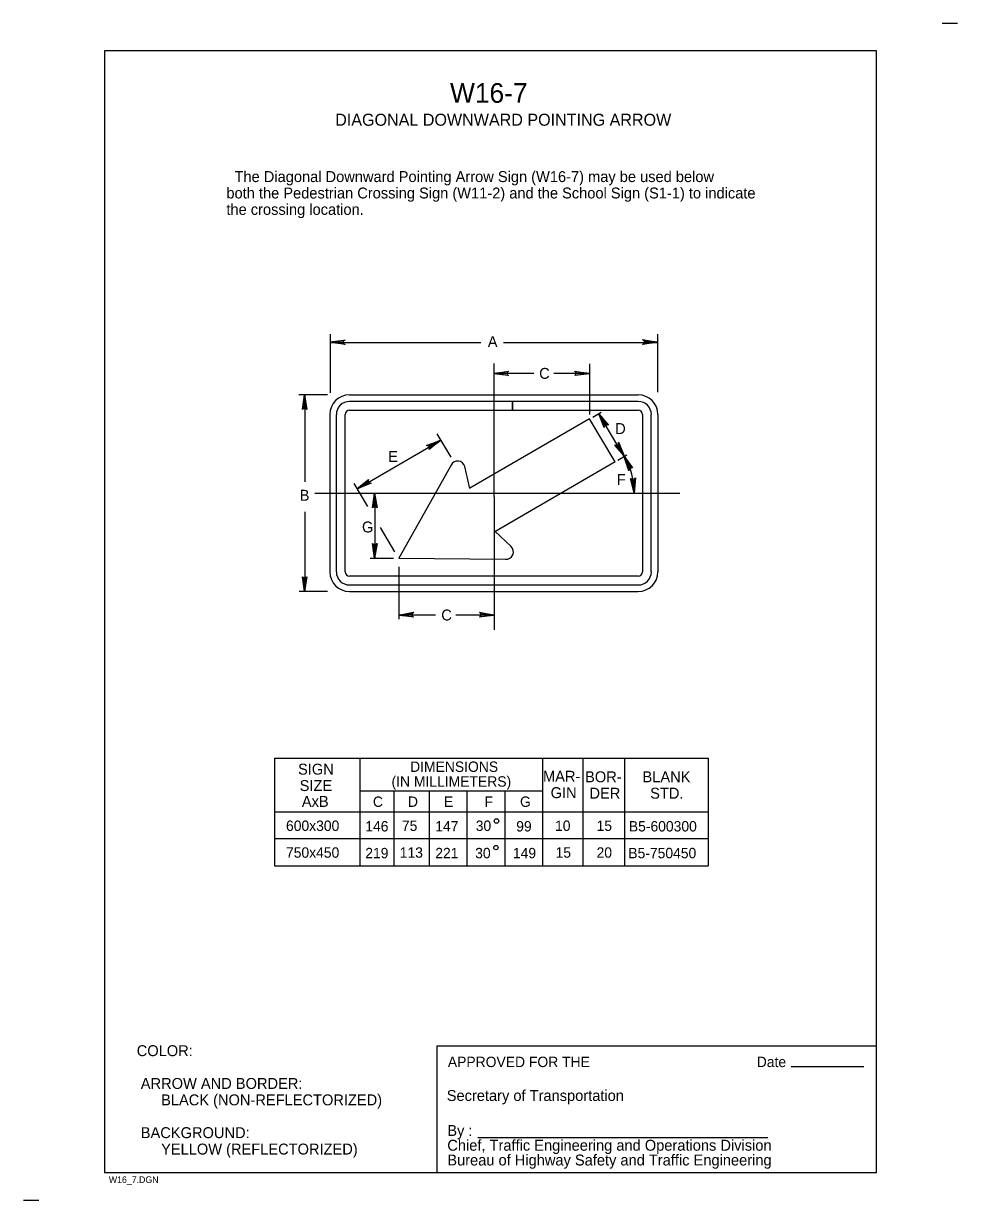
# Model space of a CAD drawing. Extents: x -0.018 to 0.195, y -0.006 to 0.263.
import ezdxf

# ---------------------------------------------------------------- set-up
doc = ezdxf.new("R2010")
doc.units = 0
for name, color, linetype in [('1', 7, 'Continuous'), ('2', 7, 'Continuous'), ('3', 7, 'Continuous')]:
    doc.layers.add(name, color=color, linetype=linetype)

msp = doc.modelspace()

# ---------------------------------------------------------------- linework, layer by layer
at = {"layer": '1'}
for p, q in [((0.195, 0.26275), (0.1915, 0.26275)), ((0.1765, 0.2565), (0, 0.2565)), ((0, 0.2565), (0, 0)), ((0.1765, 0), (0.1765, 0.2565)), ((0.076, 0.029), (0.1765, 0.029)), ((0.076, 0.029), (0.076, 0)), ((0.157, 0.02425), (0.173625, 0.02425)), ((0.085375, 0.008), (0.151625, 0.008)), ((0, 0), (0.1765, 0)), ((-0.015, -0.0063750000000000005), (-0.0185, -0.0063750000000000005))]:
    msp.add_line(p, q, dxfattribs=at)
at = {"layer": '3'}
for p, q in [((0.05156583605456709, 0.19174139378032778), (0.051565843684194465, 0.1783249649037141)), ((0.1264615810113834, 0.19174139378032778), (0.12646158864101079, 0.1784338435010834)), ((0.051565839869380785, 0.18980237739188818), (0.08602130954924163, 0.18980237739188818)), ((0.09122228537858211, 0.18980237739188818), (0.1264615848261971, 0.18980237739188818)), ((0.089, 0.185), (0.089125, 0.124125)), ((0.11089632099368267, 0.18489982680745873), (0.11089632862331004, 0.1733372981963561)), ((0.0890538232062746, 0.1827669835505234), (0.09814630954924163, 0.1827669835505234)), ((0.10274991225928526, 0.1827669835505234), (0.11089831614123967, 0.1827669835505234)), ((0.05095603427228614, 0.17783693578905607), (0.04445604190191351, 0.1778275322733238)), ((0.045771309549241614, 0.17782943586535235), (0.045771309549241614, 0.157969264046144)), ((0.056021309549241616, 0.177844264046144), (0.12202130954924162, 0.177844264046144)), ((0.09327130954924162, 0.176344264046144), (0.056021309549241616, 0.176344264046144)), ((0.09325, 0.174375), (0.09325, 0.176375)), ((0.09325, 0.176375), (0.09325, 0.174375)), ((0.12202130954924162, 0.176344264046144), (0.09327130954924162, 0.176344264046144)), ((0.05152130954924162, 0.173344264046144), (0.05152130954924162, 0.13737383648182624)), ((0.053, 0.173375), (0.053, 0.137375)), ((0.055, 0.137375), (0.055, 0.173375)), ((0.056021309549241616, 0.174344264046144), (0.09327130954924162, 0.174344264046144)), ((0.110875, 0.172375), (0.0835, 0.1565)), ((0.09327130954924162, 0.174344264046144), (0.12202130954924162, 0.174344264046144)), ((0.11674319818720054, 0.16254568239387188), (0.11089630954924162, 0.172344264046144)), ((0.1116275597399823, 0.17276722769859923), (0.11355831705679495, 0.1738839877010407)), ((0.11883977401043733, 0.16372335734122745), (0.11300722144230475, 0.17349791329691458)), ((0.123, 0.173375), (0.123, 0.137375)), ((0.125, 0.137375), (0.125, 0.173375)), ((0.12652130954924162, 0.173344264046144), (0.12652130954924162, 0.13737383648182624)), ((0.05775, 0.15637500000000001), (0.076875, 0.1675)), ((0.07922703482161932, 0.16356218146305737), (0.07604574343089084, 0.1688935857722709)), ((0.07922535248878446, 0.16175061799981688), (0.06727130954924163, 0.140469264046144)), ((0.08925, 0.146625), (0.11675, 0.162625)), ((0.11736703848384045, 0.16293883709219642), (0.11939088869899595, 0.16410944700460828)), ((0.08355640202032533, 0.15644949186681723), (0.08235821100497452, 0.1614265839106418)), ((0.060207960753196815, 0.15230646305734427), (0.05706764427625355, 0.15756920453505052)), ((0.048125, 0.155375), (0.1315, 0.155375)), ((0.06183040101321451, 0.155375), (0.06183040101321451, 0.140469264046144)), ((0.045771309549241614, 0.15106229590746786), (0.045771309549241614, 0.132844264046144)), ((0.06637259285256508, 0.1419753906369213), (0.06306720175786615, 0.14751477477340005)), ((0.0929554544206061, 0.14314292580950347), (0.08923238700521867, 0.14665659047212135)), ((0.06076507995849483, 0.140469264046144), (0.06610419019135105, 0.140469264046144)), ((0.06727130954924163, 0.140469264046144), (0.09167935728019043, 0.14026345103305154)), ((0.06727346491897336, 0.1385386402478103), (0.0672908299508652, 0.12653713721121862)), ((0.12202130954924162, 0.13637383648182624), (0.056021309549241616, 0.1363733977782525)), ((0.0510210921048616, 0.13286660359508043), (0.04452109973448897, 0.13285720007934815)), ((0.056021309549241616, 0.1343736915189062), (0.12202130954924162, 0.13437383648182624)), ((0.056021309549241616, 0.13287383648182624), (0.12202130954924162, 0.13287383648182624)), ((0.06728942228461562, 0.127509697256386), (0.07564630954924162, 0.127509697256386)), ((0.08030137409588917, 0.127509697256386), (0.08912961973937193, 0.127509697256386)), ((0.038875, 0.09475), (0.038875, 0.070125)), ((0.038875, 0.09475), (0.138, 0.09475)), ((0.058375, 0.09475), (0.058375, 0.070125)), ((0.109375, 0.09475), (0.109375, 0.070125)), ((0.11887500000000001, 0.09475), (0.11887500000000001, 0.070125)), ((0.138, 0.09475), (0.138, 0.070125)), ((0.100125, 0.08725000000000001), (0.058375, 0.08725000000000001)), ((0.038875, 0.0825), (0.138, 0.0825)), ((0.038875, 0.076375), (0.138, 0.076375)), ((0.038875, 0.070125), (0.138, 0.070125))]:
    msp.add_line(p, q, dxfattribs=at)
for points in [[(0.05475, 0.1895), (0.054625, 0.18975), (0.051500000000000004, 0.18987500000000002), (0.05475, 0.1895), (0.055, 0.18937500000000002), (0.051500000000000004, 0.18987500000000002), (0.054625, 0.19), (0.05475, 0.19025), (0.051500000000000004, 0.18987500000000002), (0.055, 0.19037500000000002), (0.05475, 0.19025)], [(0.12325, 0.19025), (0.123375, 0.19012500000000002), (0.1265, 0.18987500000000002), (0.12325, 0.19025), (0.123, 0.1905), (0.1265, 0.18987500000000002), (0.123375, 0.18975), (0.12325, 0.1895), (0.1265, 0.18987500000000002), (0.123, 0.18937500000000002), (0.12325, 0.1895)], [(0.09225, 0.182375), (0.092125, 0.182625), (0.089, 0.18275), (0.09225, 0.182375), (0.092375, 0.18225), (0.089, 0.18275), (0.092125, 0.182875), (0.09225, 0.183125), (0.089, 0.18275), (0.092375, 0.18325), (0.09225, 0.183125)], [(0.107625, 0.183125), (0.10775, 0.182875), (0.110875, 0.18275), (0.107625, 0.183125), (0.1075, 0.18325), (0.110875, 0.18275), (0.10775, 0.182625), (0.107625, 0.182375), (0.110875, 0.18275), (0.1075, 0.18225), (0.107625, 0.182375)], [(0.045375, 0.174625), (0.045625, 0.17475000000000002), (0.04575, 0.177875), (0.045375, 0.174625), (0.04525, 0.17450000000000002), (0.04575, 0.177875), (0.045875, 0.17475000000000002), (0.046125, 0.174625), (0.04575, 0.177875), (0.04625, 0.17450000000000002), (0.046125, 0.174625)], [(0.11425, 0.1705), (0.114375, 0.17075), (0.113, 0.17350000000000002), (0.11425, 0.1705), (0.11425, 0.170375), (0.113, 0.17350000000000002), (0.11475, 0.171), (0.115, 0.171), (0.113, 0.17350000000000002), (0.11525, 0.170875), (0.115, 0.171)], [(0.073875, 0.16625), (0.074125, 0.166125), (0.076875, 0.1675), (0.073875, 0.16625), (0.073625, 0.16625), (0.076875, 0.1675), (0.07425, 0.16575), (0.07425, 0.1655), (0.076875, 0.1675), (0.07425, 0.165375), (0.07425, 0.1655)], [(0.11750000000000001, 0.16675), (0.11737500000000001, 0.1665), (0.11887500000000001, 0.16375), (0.11750000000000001, 0.16675), (0.11750000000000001, 0.167), (0.11887500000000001, 0.16375), (0.117125, 0.166375), (0.116875, 0.166375), (0.11887500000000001, 0.16375), (0.116625, 0.166375), (0.116875, 0.166375)], [(0.11987500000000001, 0.16075), (0.12, 0.161), (0.11875000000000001, 0.163875), (0.11987500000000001, 0.16075), (0.11987500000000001, 0.1605), (0.11875000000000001, 0.163875), (0.12025, 0.161125), (0.1205, 0.161125), (0.11875000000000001, 0.163875), (0.12075, 0.161125), (0.1205, 0.161125)], [(0.12125, 0.15862500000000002), (0.121, 0.1585), (0.121125, 0.155375), (0.12125, 0.15862500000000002), (0.121375, 0.15887500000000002), (0.121125, 0.155375), (0.12075, 0.1585), (0.1205, 0.15862500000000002), (0.121125, 0.155375), (0.12025, 0.15875), (0.1205, 0.15862500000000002)], [(0.06075, 0.15762500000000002), (0.0605, 0.15775), (0.05775, 0.15637500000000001), (0.06075, 0.15762500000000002), (0.061, 0.15762500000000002), (0.05775, 0.15637500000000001), (0.060375, 0.15812500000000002), (0.060375, 0.15837500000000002), (0.05775, 0.15637500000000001), (0.060375, 0.1585), (0.060375, 0.15837500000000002)], [(0.061375, 0.152125), (0.061625, 0.15225), (0.06175, 0.155375), (0.061375, 0.152125), (0.06125, 0.152), (0.06175, 0.155375), (0.062, 0.15225), (0.062125, 0.152125), (0.06175, 0.155375), (0.062375, 0.152), (0.062125, 0.152125)], [(0.06225, 0.14375000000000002), (0.062, 0.143625), (0.06175, 0.1405), (0.06225, 0.14375000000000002), (0.062375, 0.143875), (0.06175, 0.1405), (0.061625, 0.143625), (0.061375, 0.14375000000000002), (0.06175, 0.1405), (0.06125, 0.143875), (0.061375, 0.14375000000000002)], [(0.046125, 0.136125), (0.045875, 0.136), (0.04575, 0.132875), (0.046125, 0.136125), (0.04625, 0.13625), (0.04575, 0.132875), (0.045625, 0.136), (0.045375, 0.136125), (0.04575, 0.132875), (0.04525, 0.13625), (0.045375, 0.136125)], [(0.07050000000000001, 0.12712500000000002), (0.07037500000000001, 0.12737500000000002), (0.06725, 0.1275), (0.07050000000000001, 0.12712500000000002), (0.07062500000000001, 0.127), (0.06725, 0.1275), (0.07037500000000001, 0.12775), (0.07050000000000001, 0.12787500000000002), (0.06725, 0.1275), (0.07062500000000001, 0.128125), (0.07050000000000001, 0.12787500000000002)], [(0.085875, 0.128), (0.08600000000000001, 0.12775), (0.089125, 0.1275), (0.085875, 0.128), (0.08575, 0.128125), (0.089125, 0.1275), (0.08600000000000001, 0.12737500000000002), (0.085875, 0.12712500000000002), (0.089125, 0.1275), (0.08575, 0.127), (0.085875, 0.12712500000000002)], [(0.100125, 0.09475), (0.100125, 0.070125)], [(0.066125, 0.08725000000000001), (0.066125, 0.070125)], [(0.07425, 0.08725000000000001), (0.07425, 0.070125)], [(0.082875, 0.08725000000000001), (0.082875, 0.070125)], [(0.0915, 0.08725000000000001), (0.0915, 0.070125)], [(0.100125, 0.08725000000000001), (0.100125, 0.070125)]]:
    msp.add_lwpolyline(points, dxfattribs=at)
for centre in [(0.08962428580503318, 0.08039836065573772), (0.0895025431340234, 0.07431229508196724)]:
    msp.add_circle(centre, 0.0005001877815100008, dxfattribs=at)
for centre, radius, start, end in [((0.056021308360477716, 0.17334426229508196), 0.0045000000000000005, 90, 180), ((0.12202130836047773, 0.17334426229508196), 0.0045000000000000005, 0, 90), ((0.056021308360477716, 0.17334426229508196), 0.003, 90, 180), ((0.12202130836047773, 0.17334426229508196), 0.003, 0, 90), ((0.056021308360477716, 0.17334426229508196), 0.001, 90, 180), ((0.12202130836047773, 0.17334426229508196), 0.001, 0, 90), ((0.08073459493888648, 0.16103571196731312), 0.00167, 13.535858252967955, 154.65382594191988), ((0.10452171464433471, 0.1553372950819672), 0.016620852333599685, 0.022005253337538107, 30.557799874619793), ((0.09180923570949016, 0.14192839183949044), 0.00167, 265.5395084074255, 46.65747609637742), ((0.056021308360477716, 0.1373738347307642), 0.0045000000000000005, 180, 270), ((0.056021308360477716, 0.1373738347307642), 0.0030001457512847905, 180, 270), ((0.056021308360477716, 0.1373738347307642), 0.001000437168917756, 180, 270), ((0.12202130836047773, 0.1373738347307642), 0.0045000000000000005, 270, 0), ((0.12202130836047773, 0.1373738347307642), 0.003, 270, 0), ((0.12202130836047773, 0.1373738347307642), 0.001, 270, 0)]:
    msp.add_arc(centre, radius, start, end, dxfattribs=at)

# ---------------------------------------------------------------- texts
at = {"layer": '1'}
for s, height, p in [('W16-7', 0.0045000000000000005, (0.079, 0.244625)), ('DIAGONAL DOWNWARD POINTING ARROW', 0.00275025, (0.05275, 0.239375)), ('COLOR:', 0.0024997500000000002, (0.0073750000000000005, 0.026625)), ('APPROVED FOR THE', 0.0023752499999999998, (0.0785, 0.024125)), ('Date ', 0.0023752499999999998, (0.149125, 0.024125)), (' ARROW AND BORDER:', 0.0024997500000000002, (0.0073750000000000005, 0.019125)), ('Secretary of Transportation', 0.0024997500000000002, (0.07825, 0.016375)), ('      BLACK (NON-REFLECTORIZED)', 0.0024997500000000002, (0.0073750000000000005, 0.015375)), ('By :', 0.0024997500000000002, (0.078375, 0.008375)), (' BACKGROUND:', 0.0024997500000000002, (0.0073750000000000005, 0.007875)), ('      YELLOW (REFLECTORIZED)', 0.0024997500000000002, (0.0073750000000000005, 0.004125)), ('Chief, Traffic Engineering and Operations Division', 0.0024997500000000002, (0.078375, 0.005)), ('Bureau of Highway Safety and Traffic Engineering', 0.0024997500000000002, (0.078375, 0.0016250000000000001)), ('W16_7.DGN', 0.0015, (0.001, -0.002375))]:
    msp.add_text(s, height=height, dxfattribs=at).set_placement(p)
at = {"layer": '2'}
for s, p in [('  The Diagonal Downward Pointing Arrow Sign (W16-7) may be used below', (0.027875, 0.2265)), ('both the Pedestrian Crossing Sign (W11-2) and the School Sign (S1-1) to indicate', (0.027875, 0.22275)), ('the crossing location.', (0.027875, 0.219))]:
    msp.add_text(s, height=0.0024997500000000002, dxfattribs=at).set_placement(p)
at = {"layer": '3'}
for s, rotation, p in [('A', 359.9170833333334, (0.08762500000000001, 0.18875)), ('C', 0.08291666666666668, (0.099375, 0.1815)), ('D', 0.08291666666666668, (0.11675, 0.168875)), ('E', 0.08291666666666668, (0.064875, 0.1625)), ('F', 0.08291666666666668, (0.117125, 0.15725)), ('B', 0.08291666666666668, (0.044625, 0.153625)), ('G', 0.08291666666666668, (0.058875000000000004, 0.146375)), ('C', 0.08291666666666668, (0.077, 0.12625))]:
    msp.add_text(s, height=0.0024997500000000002, rotation=rotation, dxfattribs=at).set_placement(p)
for s, height, p in [('SIGN', 0.0024997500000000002, (0.04425, 0.091)), ('DIMENSIONS', 0.0023752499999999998, (0.069875, 0.091625)), ('MAR-', 0.0024997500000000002, (0.10025, 0.089375)), ('BOR-', 0.0024997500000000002, (0.109875, 0.08925)), ('BLANK', 0.0024997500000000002, (0.123, 0.08925)), ('SIZE', 0.0024997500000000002, (0.044625, 0.08725000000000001)), ('(IN MILLIMETERS)', 0.0023752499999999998, (0.065625, 0.08825)), ('AxB', 0.0024997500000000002, (0.045125, 0.083625)), ('GIN', 0.0024997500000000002, (0.10200000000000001, 0.085625)), ('DER', 0.0024997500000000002, (0.110875, 0.0855)), ('STD.', 0.0024997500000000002, (0.12475, 0.0855)), ('C', 0.0023752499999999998, (0.061375, 0.083625)), ('D', 0.0023752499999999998, (0.069375, 0.083625)), ('E', 0.0023752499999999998, (0.077625, 0.083625)), ('F', 0.0023752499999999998, (0.08687500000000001, 0.083625)), ('G', 0.0023752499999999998, (0.095, 0.083625)), ('600x300', 0.0023752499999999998, (0.0415, 0.078125)), ('146', 0.0023752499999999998, (0.059625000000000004, 0.078)), ('75', 0.0023752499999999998, (0.068, 0.078125)), ('147', 0.0023752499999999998, (0.075625, 0.078)), ('30', 0.0023752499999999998, (0.084875, 0.078125)), ('99', 0.0023752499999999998, (0.094125, 0.078)), ('10', 0.0023752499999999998, (0.10300000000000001, 0.078125)), ('15', 0.0023752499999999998, (0.1125, 0.078125)), ('B5-600300', 0.0023752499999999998, (0.11987500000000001, 0.078)), ('750x450', 0.0023752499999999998, (0.0415, 0.07200000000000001)), ('219', 0.0023752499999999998, (0.059625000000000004, 0.07187500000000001)), ('113', 0.0023752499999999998, (0.0675, 0.07200000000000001)), ('221', 0.0023752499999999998, (0.075625, 0.07187500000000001)), ('30', 0.0023752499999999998, (0.08475, 0.07187500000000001)), ('149', 0.0023752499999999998, (0.093375, 0.07187500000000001)), ('15', 0.0023752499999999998, (0.10312500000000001, 0.07200000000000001)), ('20', 0.0023752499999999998, (0.1125, 0.07200000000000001)), ('B5-750450', 0.0023752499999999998, (0.11975000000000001, 0.07187500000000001))]:
    msp.add_text(s, height=height, dxfattribs=at).set_placement(p)

doc.saveas('drawing.dxf')
